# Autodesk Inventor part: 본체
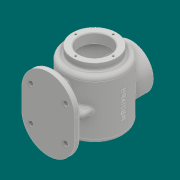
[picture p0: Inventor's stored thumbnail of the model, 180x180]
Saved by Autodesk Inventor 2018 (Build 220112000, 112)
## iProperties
Created: 2023-01
Part Number: 본체
Material: 일반
Document SubType Name: Modeling
Designer: 강의실01
Density: 1 g/cm^3
Appearance: 기본값
Author: 강의실01
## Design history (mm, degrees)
sketch "스케치1"
  geometry: L1 (0, 17)-(0, -17); L2 (-46, 17)-(-46, -17); L3 (46, -17)-(46, 17); C1 r 4.5 at (30, 30); C2 r 4.5 at (30, -30); C3 r 4.5 at (-30, 30); C4 r 4.5 at (-30, -30); A1 r 46 centre (0, 17) between (46, 17) and (-46, 17); A2 r 46 centre (0, -17) between (-46, -17) and (46, -17); 2 further points
  constraints: 8 end point, 6 centre point, 4 point on circle, 4 tangent, 2 coincident, 2 horizontal alignment, 2 vertical alignment, 1 midpoint, 1 parallel, 1 vertical
  dimensions: "d0" = 92 distance between parallel lines of L2 L3; "d1" = 34 distance of L1.end L1.start; "d2" = 126 dimension on A2 A1 (derived); "d3" = 9 diameter of C1; "d4" = 9 diameter of C2; "d5" = 9 diameter of C3; "d6" = 9 diameter of C4; "d7" = 30 horizontal distance of point (0, 0) C1.centre; "d8" = 30 horizontal distance of C2.centre point (0, 0); "d9" = 30 horizontal distance of C1.centre point (0, 0); "d10" = 30 horizontal distance of C3.centre point (0, 0)
extrude "돌출1" new body sketch "스케치1" distance "d11" = 10; taper "d12" = 0 deg
sketch "스케치3" dims "d0" = 92, "d1" = 34, "d2" = 126 (derived)
  geometry: L1 (80, 181)-(80, -59); L2 (0, -17)-(0, 17) reference; L3 (107, 63)-(118, 63) reference; L4 (118, 63)-(118, 51); L5 (118, 51)-(122, 51); L6 (130, 43)-(130, -42.827); L7 (107, 63)-(107, 46); L8 (125, -42.827)-(125, 43); L9 (122, 46)-(107, 46); A1 r 120 centre (80, 61) between (80, -59) and (125, -50.243); A2 r 8 centre (122, -42.827) between (125, -50.243) and (130, -42.827); A3 r 8 centre (122, 43) between (130, 43) and (122, 51); A4 r 115 centre (80, 61) between (80, -54) and (123.125, -45.608); A5 r 3 centre (122, -42.827) between (123.125, -45.608) and (125, -42.827); A6 r 3 centre (122, 43) between (125, 43) and (122, 46); 2 further points
  constraints: 16 end point, 13 point on circle, 6 centre point, 6 tangent, 4 perpendicular, 2 horizontal, 2 point on line, 1 vertical, 2 other
  dimensions: "d18" = 80 distance between parallel lines of L2 L1; "d19" = 76 diameter of L4 L1; "d20" = 100 diameter of L6 L1; "d21" = 12 distance of L3.end L4.end; "d24" = 8 radius of A2; "d25" = 8 radius of A3 (derived); "d27" = 54 diameter of L7 L1; "d33" = 120 radius of A1; "d35" = 122 distance from line of L1.end L3; "d36" = 5 distance between parallel lines of L6 L8; "d38" = 105.82678 distance from line of L6.end L3; "d39" = 118 distance from line of L1.start L3
revolve "회전1" sketch "스케치3" stored, may be unused: angle "d37" = 90 deg
sketch "스케치4"
  geometry: L1 (30, 43)-(30, -42.827) reference; L2 (10, 17)-(10, 63) reference; L3 (10, -63)-(10, -17) reference; L4 (10, 40)-(30, 34.641); L5 (10, -40)-(30, -34.641); L6 (0, 63)-(10, 63) reference; 1 further point
  constraints: 4 end point, 2 midpoint, 2 point on line
  dimensions: "d40" = 23 distance from line of L4.start L6; "d41" = 80 distance of L5.start L4.start; "d42" = 105 deg angle of L2 L4; "d43" = 105 deg angle of L3 L5
node "작업 평면1"
sketch "스케치5"
  geometry: L1 (-42, 51)-(42, 51) reference; C1 r 38 at (0, 0); 1 further point
  constraints: 1 centre point, 1 coincident
  dimensions: "d57" = 76 diameter of C1; "d58" = 51 distance from line of C1.centre L1
extrude "돌출3" join sketch "스케치5" stored distance "d59" = 70; taper "d60" = 0 deg
sketch "스케치6"
  geometry: L1 (-30, 0)-(30, 0); L2 (-30, -5)-(30, -5); L3 (30, 5)-(-30, 5); A1 r 5 centre (-30, 0) between (-30, 5) and (-30, -5); A2 r 5 centre (30, 0) between (30, -5) and (30, 5); 2 further points
  constraints: 8 end point, 4 point on circle, 4 tangent, 2 centre point, 2 coincident, 1 horizontal, 1 midpoint, 1 parallel
  dimensions: "d61" = 10 diameter of A2; "d62" = 30 distance of L1.start point (0, 0)
extrude "돌출4" join sketch "스케치6" stored distance "d63" = 70; taper "d64" = 0 deg
feature "리브3" dims "d65" = 1, "d66" = 10, "d67" = 0, "d68" = 0, "d69" = 1, "d70" = 1
feature "리브4" dims "d71" = 1, "d72" = 10, "d73" = 0, "d74" = 0, "d75" = 1, "d76" = 1
hole "구멍1" diameter "d79" = 54; stored, may be unused: countersink angle "d83" = 90 deg, drill point angle "d85" = 0 deg; dims "d77" = 10, "d78" = 10, "d80" = 6, "d81" = 4, "d82" = 2, "d84" = 50
sketch "스케치7"
  geometry: 2 further points
  constraints: 1 horizontal alignment
  dimensions: "d86" = 32.5 distance of point (0, 0) point (-32.5, 0)
hole "구멍2" sketch "스케치7" at (-32.5, 0) diameter "d87" = 3.242; stored, may be unused: countersink angle "d91" = 90 deg, drill point angle "d93" = 118 deg; dims "d88" = 8, "d89" = 4, "d90" = 2, "d92" = 10
sketch "스케치8"
  geometry: C1 r 27 at (0, 0) reference; 2 further points
  constraints: 1 vertical alignment
  dimensions: "d97" = 32.5 distance of C1.centre point (0, 32.5)
hole "구멍3" sketch "스케치8" at (0, 32.5) diameter "d98" = 3.242; stored, may be unused: countersink angle "d102" = 90 deg, drill point angle "d104" = 118 deg; dims "d99" = 8, "d100" = 4, "d101" = 2, "d103" = 10
node "작업 평면2"
sketch "스케치9"
  geometry: L1 (42, 63)-(118, 63) reference; L2 (0, 17)-(0, -17) reference; 3 further points
  constraints: 1 midpoint, 1 vertical alignment, 1 other
  dimensions: "d109" = 63 distance from line of point (80, 0) L1; "d115" = 80 distance from line of L2 point (80, 0) (derived)
feature "엠보싱1" sketch "스케치9" dims "d0" = 92, "d1" = 34, "d2" = 126 (derived), "d18" = 80, "d19" = 76, "d20" = 100, "d21" = 12, "d24" = 8, "d25" = 8 (derived), "d27" = 54, "d33" = 120, "d35" = 122, "d36" = 5, "d38" = 105.82678, "d39" = 118, "d110" = 0.5, "d111" = 0
chamfer "모따기1" distance "d112" = 1; stored, may be unused: second distance "d113" = 2, angle "d114" = 45 deg
fillet "모깎기1" dims "d116" = 3
node "솔리드1"
pattern_circular "원형 패턴1" dims angle "d95" = 360 deg
pattern_circular "원형 패턴2" dims angle "d106" = 360 deg
other parameters: "d56" = 144
